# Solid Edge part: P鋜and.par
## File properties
Author: Türk
Template: iso part.par
Last saved by: Türk
Revision: 46
Application: Solid Edge
Accuracy: 0,990
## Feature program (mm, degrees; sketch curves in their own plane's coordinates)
base feature "unnamed BaseFeature 1"
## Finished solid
Body 1: sheet body, 2 faces, 22 edges, 22 vertices.
  Faces by surface: plane 2
  Edges by curve: line 22
Body 2: solid body, 130 faces, 354 edges, 224 vertices.
  Faces by surface: plane 61, cylinder 37, spline 14, sphere 8, torus 5, cone 3, swept 2
  Edges by curve: line 219, circle 93, intersection 20, spline 14, curve on surface 4, ellipse 4
Bounding box of the edges (mm; curved faces can reach further): 1290.311 x 1670.000 x 550.000, from (-645.1556, 850, -100) to (645.1556, 2520, 450).
Cylindrical faces by radius (mm): R8 x4, R50 x24, R90 x1, R100 x1, R183.3721 x1, R193.3721 x1, R269.8151 x3, R279.8151 x2
Conical faces (half-angle, radius in mm at the cone's reference point): 20 deg R193.3721 x1, 20 deg R269.8151 x1, 45 deg R178.3721 x1
Toroidal faces (ring radius, tube radius in mm): R150 r50 x1, R243.3721 r50 x2, R319.8151 r50 x2
Spherical faces by radius (mm): R50 x8
Planar faces by outward normal: +x 6, +y 10, +z 8, -x 6, -y 11, -z 7, oblique 13
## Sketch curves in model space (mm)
line (0, 1100, 400) -> (-150, 1100, 400)
line (600, 1100, 400) -> (600, 1100, -75)
line (-600, 1100, -75) -> (-600, 1100, 400)
line (-563.4665, 1075, 338.0385) -> (-588.4665, 1075, 338.0385)
line (-315.8824, 1075, -75) -> (-269.8151, 1075, -75)
arc centre (0, 1075, -75) radius 269.8151 from (-269.6297, 1075, -65) through (-269.7687, 1075, -69.9991) to (-269.8151, 1075, -75)
arc centre (-235.9581, 1075, -332.7058) radius 269.8151 from (-269.6297, 1075, -65) through (-292.9757, 1075, -68.984) to (-315.8824, 1075, -75)
line (0, 1607.5, -75) -> (0, 1227.9742, -75)
arc centre (0, 1050, -75) radius 269.8151 from (-269.8151, 1050, -75) through (7.9955, 1050, 194.6966) to (269.8151, 1050, -75)
line (-588.4665, 1050, -75) -> (-269.8151, 1050, -75)
line (-588.4665, 1050, 338.0385) -> (-588.4665, 1050, -75)
line (-563.4665, 1050, 338.0385) -> (-588.4665, 1050, 338.0385)
line (-113.4665, 1050, 338.0385) -> (-563.4665, 1050, 338.0385)
line (-247.0928, 1050, 33.3759) -> (-113.4665, 1050, 338.0385)
arc centre (0, 1050, -75) radius 269.8151 from (-247.0928, 1050, 33.3759) through (-264.0734, 1050, -19.6338) to (-269.8151, 1050, -75)
line (588.4665, 1050, -75) -> (269.8151, 1050, -75)
line (588.4665, 1050, 338.0385) -> (588.4665, 1050, -75)
line (563.4665, 1050, 338.0385) -> (588.4665, 1050, 338.0385)
line (113.4665, 1050, 338.0385) -> (563.4665, 1050, 338.0385)
line (247.0928, 1050, 33.3759) -> (113.4665, 1050, 338.0385)
arc centre (0, 1050, -75) radius 269.8151 from (247.0928, 1050, 33.3759) through (264.0734, 1050, -19.6338) to (269.8151, 1050, -75)
line (-183.3721, 1337.5, -75) -> (-183.3721, 1337.5, 5)
arc centre (0, 1337.5, 5) radius 183.3721 from (183.3721, 1337.5, 5) through (-5.4339, 1337.5, 188.2916) to (-183.3721, 1337.5, 5)
line (-173.3721, 1337.5, -100) -> (-183.3721, 1337.5, -100)
line (-173.3721, 1337.5, 5) -> (-173.3721, 1337.5, -100)
arc centre (0, 1337.5, 5) radius 173.3721 from (173.3721, 1337.5, 5) through (-5.1376, 1337.5, 178.296) to (-173.3721, 1337.5, 5)
line (173.3721, 1337.5, -75) -> (173.3721, 1337.5, 5)
line (173.3721, 1337.5, -100) -> (173.3721, 1337.5, -75)
line (183.3721, 1337.5, -100) -> (173.3721, 1337.5, -100)
line (183.3721, 1337.5, -75) -> (183.3721, 1337.5, -100)
line (183.3721, 1337.5, -75) -> (183.3721, 1337.5, 5)
line (-183.3721, 1337.5, -75) -> (-173.3721, 1337.5, -75)
line (183.3721, 1607.5, -100) -> (183.3721, 1607.5, -75)
line (183.3721, 1607.5, -100) -> (173.3721, 1607.5, -100)
line (173.3721, 1607.5, -75.688) -> (173.3721, 1607.5, -100)
arc centre (0, 1607.5, -100) radius 175.0685 from (-173.3721, 1607.5, -75.688) through (0, 1607.5, 75.0685) to (173.3721, 1607.5, -75.688)
line (-173.3721, 1607.5, -100) -> (-173.3721, 1607.5, -75.688)
line (-173.3721, 1607.5, -100) -> (-183.3721, 1607.5, -100)
line (-183.3721, 1607.5, -75) -> (-183.3721, 1607.5, -100)
arc centre (0, 1607.5, -100) radius 185.0685 from (-183.3721, 1607.5, -75) through (0, 1607.5, 85.0685) to (183.3721, 1607.5, -75)
arc centre (529.3774, 2420, 550) radius 100 from (628.6052, 2432.4035, 550) through (593.3616, 2496.8507, 550) to (529.3774, 2520, 550)
line (529.3774, 2520, 550) -> (0, 2520, 550)
line (-529.3774, 2520, 550) -> (0, 2520, 550)
arc centre (-529.3774, 2420, 550) radius 100 from (-628.6052, 2432.4035, 550) through (-593.3616, 2496.8507, 550) to (-529.3774, 2520, 550)
line (-645.1556, 2300, 550) -> (-628.6052, 2432.4035, 550)
line (-645.1556, 2300, 550) -> (-604.8444, 2300, 550)
line (-604.8444, 2300, 550) -> (-588.9141, 2427.4421, 550)
arc centre (-529.3774, 2420, 550) radius 60 from (-588.9141, 2427.4421, 550) through (-567.7679, 2466.1104, 550) to (-529.3774, 2480, 550)
line (-529.3774, 2480, 550) -> (0, 2480, 550)
line (529.3774, 2480, 550) -> (0, 2480, 550)
arc centre (529.3774, 2420, 550) radius 60 from (588.9141, 2427.4421, 550) through (567.7679, 2466.1104, 550) to (529.3774, 2480, 550)
line (604.8444, 2300, 550) -> (588.9141, 2427.4421, 550)
line (645.1556, 2300, 550) -> (604.8444, 2300, 550)
line (645.1556, 2300, 550) -> (628.6052, 2432.4035, 550)
line (-650, 2300, -100) -> (-600, 2300, -100)
line (-183.3721, 1617.5, -100) -> (183.3721, 1617.5, -100)
line (600, 2300, -100) -> (650, 2300, -100)
line (-550, 2300, -100) -> (-550, 2260, -100)
line (-550, 2260, -100) -> (-550, 2260, 150)
line (-550, 2260, 150) -> (-550, 2300, 150)
line (-550, 2300, 150) -> (-550, 2300, -100)
line (0, 2260, 150) -> (0, 2300, 150)
line (0, 2300, 150) -> (0, 2300, -100)
line (0, 2300, -100) -> (0, 2260, -100)
line (0, 2260, -100) -> (0, 2260, 150)
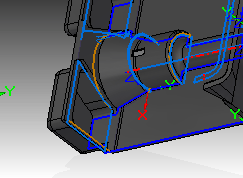
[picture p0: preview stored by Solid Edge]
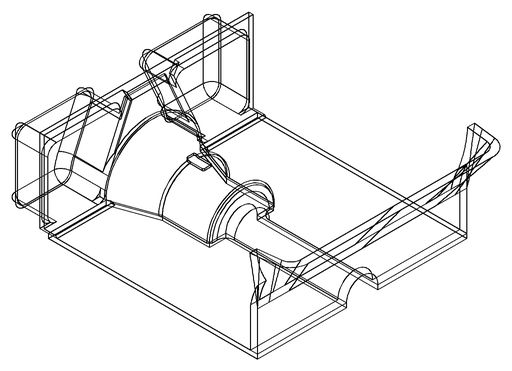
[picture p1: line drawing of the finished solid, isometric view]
